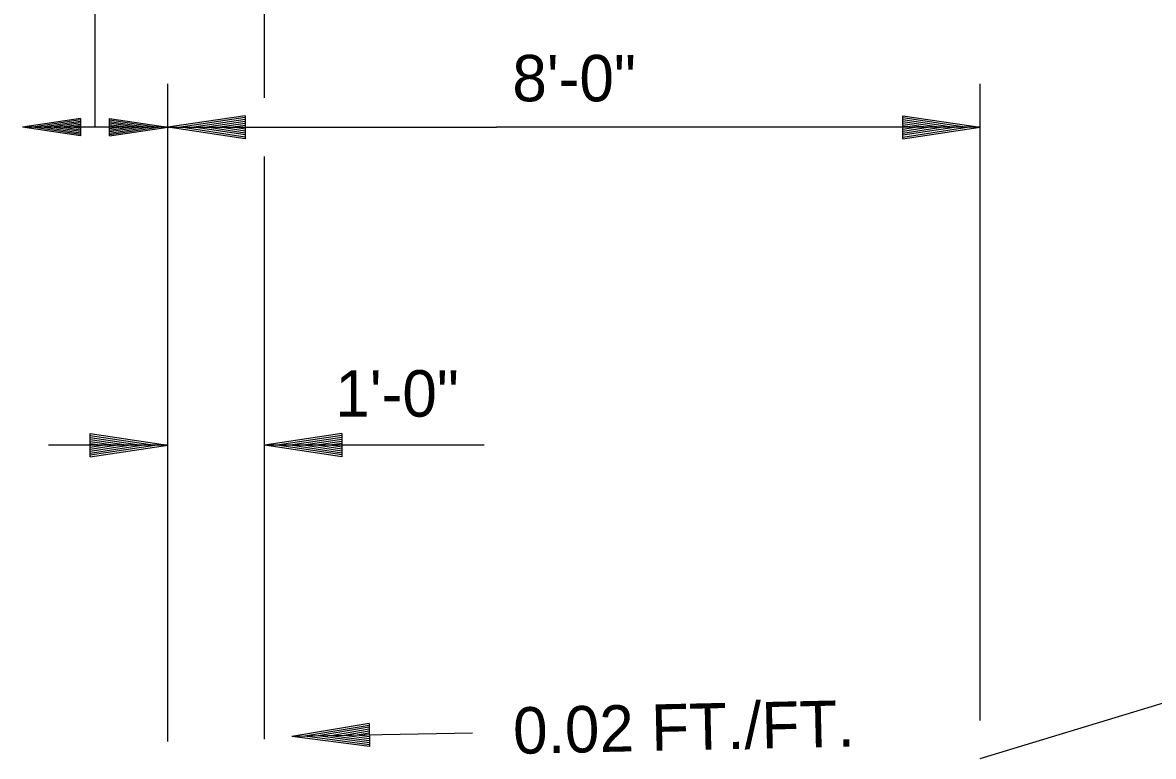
# Model space of a CAD drawing. Extents: x 635488 to 635865, y 290537 to 290973.
# Drawn here: x 635719.55 to 635734.16, y 290670.31 to 290679.79 of the extents above; entities that cross this region are included whole.
import ezdxf

# ---------------------------------------------------------------- set-up
doc = ezdxf.new("R2010")
doc.units = 0
for name, color, linetype in [('Level 13', 7, 'Continuous'), ('Level 43', 7, 'Continuous'), ('R_Border', 7, 'Continuous'), ('R_Dimension', 7, 'Continuous')]:
    doc.layers.add(name, color=color, linetype=linetype)

msp = doc.modelspace()

# ---------------------------------------------------------------- linework, layer by layer
at = {"layer": 'Level 43'}
for p, q in [((635720.489, 290678.439), (635720.489, 290691.21)), ((635722.676, 290678.818), (635722.676, 290690.273)), ((635721.426, 290670.5), (635721.426, 290678.999)), ((635731.926, 290670.77), (635731.926, 290678.999)), ((635721.426, 290678.439), (635719.551, 290678.439)), ((635721.427, 290678.438), (635725.677, 290678.438)), ((635731.927, 290678.438), (635725.677, 290678.438)), ((635722.676, 290670.53), (635722.676, 290678.059)), ((635721.426, 290674.329), (635719.884, 290674.329)), ((635725.514, 290674.329), (635722.676, 290674.329)), ((635725.367, 290670.609), (635723.031, 290670.566))]:
    msp.add_line(p, q, dxfattribs=at)
at = {"layer": 'R_Border'}
msp.add_line((635731.927, 290670.282), (635740.284, 290672.815), dxfattribs=at)
at = {"layer": 'R_Dimension'}
for p, q in [((635720.301, 290678.551), (635719.551, 290678.439)), ((635720.301, 290678.533), (635719.677, 290678.439)), ((635720.301, 290678.551), (635720.301, 290678.326)), ((635720.676, 290678.551), (635721.426, 290678.439)), ((635720.676, 290678.326), (635720.676, 290678.551)), ((635720.676, 290678.533), (635721.301, 290678.439)), ((635722.427, 290678.588), (635721.427, 290678.438)), ((635722.427, 290678.563), (635721.594, 290678.438)), ((635722.427, 290678.538), (635721.766, 290678.438)), ((635722.427, 290678.588), (635722.427, 290678.288)), ((635730.927, 290678.588), (635731.927, 290678.438)), ((635730.927, 290678.288), (635730.927, 290678.588)), ((635730.927, 290678.563), (635731.76, 290678.438)), ((635730.927, 290678.538), (635731.588, 290678.438)), ((635720.301, 290678.326), (635719.551, 290678.439)), ((635720.301, 290678.345), (635719.677, 290678.439)), ((635720.301, 290678.513), (635719.806, 290678.439)), ((635720.301, 290678.364), (635719.806, 290678.439)), ((635720.301, 290678.495), (635719.931, 290678.439)), ((635720.301, 290678.383), (635719.931, 290678.439)), ((635720.301, 290678.475), (635720.058, 290678.439)), ((635720.301, 290678.402), (635720.058, 290678.439)), ((635720.301, 290678.456), (635720.183, 290678.439)), ((635720.301, 290678.421), (635720.183, 290678.439)), ((635720.676, 290678.513), (635721.172, 290678.439)), ((635720.676, 290678.495), (635721.047, 290678.439)), ((635720.676, 290678.476), (635720.92, 290678.439)), ((635720.676, 290678.456), (635720.795, 290678.439)), ((635720.676, 290678.326), (635721.426, 290678.439)), ((635720.676, 290678.402), (635720.92, 290678.439)), ((635720.676, 290678.364), (635721.172, 290678.439)), ((635720.676, 290678.345), (635721.301, 290678.439)), ((635720.676, 290678.383), (635721.047, 290678.439)), ((635720.676, 290678.421), (635720.795, 290678.439)), ((635722.427, 290678.288), (635721.427, 290678.438)), ((635722.427, 290678.313), (635721.594, 290678.438)), ((635722.427, 290678.339), (635721.766, 290678.438)), ((635722.427, 290678.513), (635721.933, 290678.438)), ((635722.427, 290678.364), (635721.933, 290678.438)), ((635722.427, 290678.487), (635722.102, 290678.438)), ((635722.427, 290678.389), (635722.102, 290678.438)), ((635722.427, 290678.462), (635722.269, 290678.438)), ((635722.427, 290678.415), (635722.269, 290678.438)), ((635730.927, 290678.513), (635731.422, 290678.438)), ((635730.927, 290678.487), (635731.252, 290678.438)), ((635730.927, 290678.462), (635731.085, 290678.438)), ((635730.927, 290678.288), (635731.927, 290678.438)), ((635730.927, 290678.39), (635731.252, 290678.438)), ((635730.927, 290678.339), (635731.588, 290678.438)), ((635730.927, 290678.313), (635731.76, 290678.438)), ((635730.927, 290678.364), (635731.422, 290678.438)), ((635730.927, 290678.415), (635731.085, 290678.438)), ((635720.426, 290674.479), (635721.426, 290674.329)), ((635720.426, 290674.179), (635720.426, 290674.479)), ((635720.426, 290674.454), (635721.259, 290674.329)), ((635723.676, 290674.479), (635722.676, 290674.329)), ((635723.676, 290674.454), (635722.843, 290674.329)), ((635723.676, 290674.479), (635723.676, 290674.179)), ((635720.426, 290674.428), (635721.087, 290674.329)), ((635720.426, 290674.403), (635720.921, 290674.329)), ((635720.426, 290674.378), (635720.751, 290674.329)), ((635720.426, 290674.352), (635720.584, 290674.329)), ((635720.426, 290674.179), (635721.426, 290674.329)), ((635720.426, 290674.28), (635720.751, 290674.329)), ((635720.426, 290674.229), (635721.087, 290674.329)), ((635720.426, 290674.204), (635721.259, 290674.329)), ((635720.426, 290674.254), (635720.921, 290674.329)), ((635720.426, 290674.305), (635720.584, 290674.329)), ((635723.676, 290674.179), (635722.676, 290674.329)), ((635723.676, 290674.204), (635722.843, 290674.329)), ((635723.676, 290674.428), (635723.015, 290674.329)), ((635723.676, 290674.229), (635723.015, 290674.329)), ((635723.676, 290674.403), (635723.181, 290674.329)), ((635723.676, 290674.254), (635723.181, 290674.329)), ((635723.676, 290674.377), (635723.351, 290674.329)), ((635723.676, 290674.28), (635723.351, 290674.329)), ((635723.676, 290674.352), (635723.518, 290674.329)), ((635723.676, 290674.305), (635723.518, 290674.329)), ((635724.028, 290670.734), (635723.031, 290670.566)), ((635724.028, 290670.709), (635723.198, 290670.569)), ((635724.029, 290670.684), (635723.37, 290670.572)), ((635724.029, 290670.659), (635723.536, 290670.575)), ((635724.028, 290670.734), (635724.034, 290670.434)), ((635724.034, 290670.434), (635723.031, 290670.566)), ((635724.033, 290670.459), (635723.198, 290670.569)), ((635724.033, 290670.485), (635723.37, 290670.572)), ((635724.032, 290670.51), (635723.536, 290670.575)), ((635724.03, 290670.633), (635723.706, 290670.578)), ((635724.032, 290670.535), (635723.706, 290670.578)), ((635724.03, 290670.608), (635723.873, 290670.581)), ((635724.031, 290670.561), (635723.873, 290670.581))]:
    msp.add_line(p, q, dxfattribs=at)

# ---------------------------------------------------------------- texts
at = {"layer": 'Level 13'}
for s, p in [('8\'-0"', (635725.88, 290678.774)), ('1\'-0"', (635723.592, 290674.699))]:
    msp.add_text(s, height=0.6, dxfattribs=at).set_placement(p)
msp.add_text('0.02 FT./FT.', height=0.6, rotation=1.2499, dxfattribs=at).set_placement((635725.896, 290670.34))

doc.saveas('drawing.dxf')
